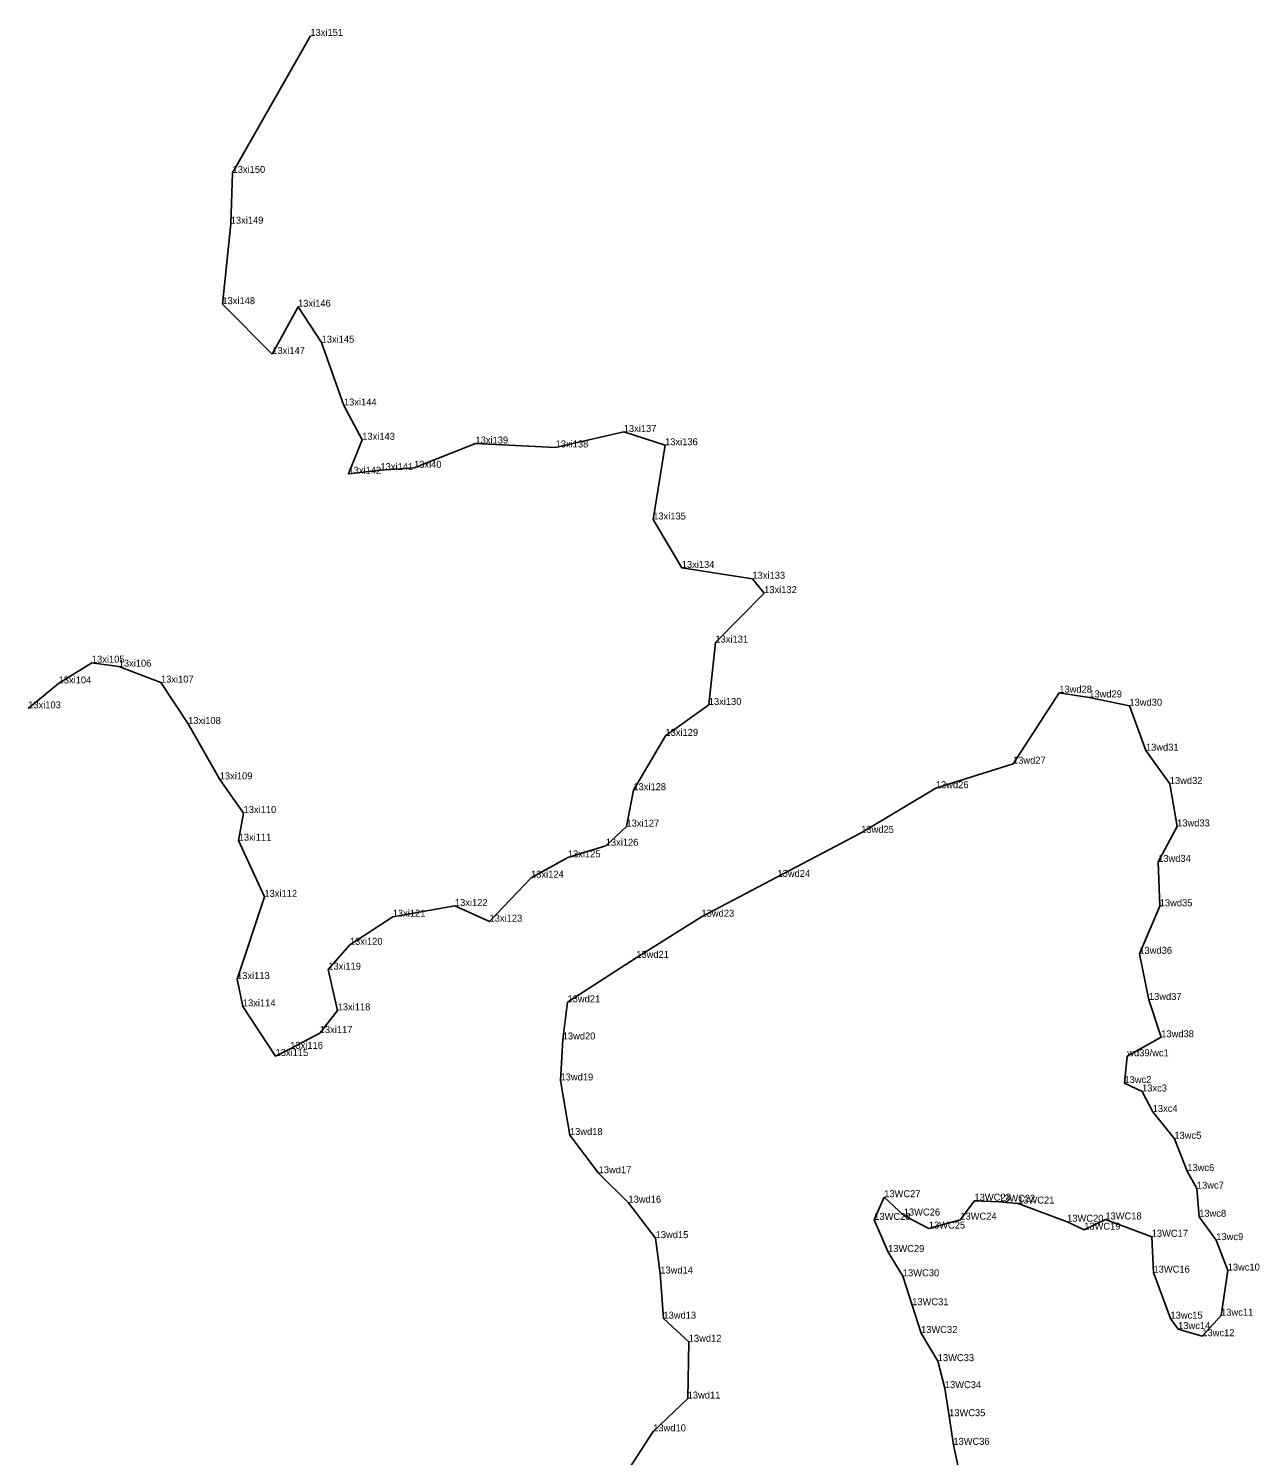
# Model space of a CAD drawing. Extents: x 2072529 to 2267990, y 436423 to 470008.
# Drawn here: x 2249662 to 2250544, y 445372 to 446395 of the extents above; entities that cross this region are included whole.
import ezdxf

# ---------------------------------------------------------------- set-up
doc = ezdxf.new("R2010")
doc.units = 0
doc.layers.add('Level 3', color=7, linetype='Continuous')
doc.layers.add('Old_Level_52', color=7, linetype='Continuous')

msp = doc.modelspace()

# ---------------------------------------------------------------- linework, layer by layer
at = {"layer": 'Level 3'}
for p, q in [((2249864.054, 446389.51), (2249864.054, 446389.51)), ((2249808.263, 446291.367), (2249808.263, 446291.367)), ((2249806.952, 446254.92), (2249806.952, 446254.92)), ((2249800.992, 446197.275), (2249800.992, 446197.275)), ((2249855.211, 446195.401), (2249855.211, 446195.401)), ((2249836.743, 446161.549), (2249836.743, 446161.549)), ((2249872.104, 446169.706), (2249872.104, 446169.706)), ((2249888.108, 446124.67), (2249888.108, 446124.67)), ((2250088.644, 446105.724), (2250088.644, 446105.724)), ((2249901.206, 446100.088), (2249901.206, 446100.088)), ((2249982.375, 446097.438), (2249982.375, 446097.438)), ((2250039.816, 446094.602), (2250039.816, 446094.602)), ((2250118.26, 446096.199), (2250118.26, 446096.199)), ((2249938.334, 446080.021), (2249938.334, 446080.021)), ((2249891.368, 446075.752), (2249891.368, 446075.752)), ((2249914.268, 446078.351), (2249914.268, 446078.351)), ((2250109.758, 446042.981), (2250109.758, 446042.981)), ((2250130.226, 446008.305), (2250130.226, 446008.305)), ((2250180.892, 446000.528), (2250180.892, 446000.528)), ((2250189.242, 445990.208), (2250189.242, 445990.208)), ((2250154.331, 445954.77), (2250154.331, 445954.77)), ((2249707.449, 445940.391), (2249707.449, 445940.391)), ((2249726.667, 445937.537), (2249726.667, 445937.537)), ((2249683.597, 445925.496), (2249683.597, 445925.496)), ((2249756.958, 445926.078), (2249756.958, 445926.078)), ((2250400.808, 445918.894), (2250400.808, 445918.894)), ((2250149.577, 445910.129), (2250149.577, 445910.129)), ((2250422.252, 445915.472), (2250422.252, 445915.472)), ((2250451.071, 445909.522), (2250451.071, 445909.522)), ((2249776.429, 445896.462), (2249776.429, 445896.462)), ((2250118.522, 445887.955), (2250118.522, 445887.955)), ((2250462.899, 445877.362), (2250462.899, 445877.362)), ((2250367.641, 445867.985), (2250367.641, 445867.985)), ((2249799.095, 445856.755), (2249799.095, 445856.755)), ((2250095.551, 445849.029), (2250095.551, 445849.029)), ((2250312.343, 445850.441), (2250312.343, 445850.441)), ((2250480.028, 445853.489), (2250480.028, 445853.489)), ((2249816.152, 445832.664), (2249816.152, 445832.664)), ((2250090.612, 445822.894), (2250090.612, 445822.894)), ((2250258.827, 445818.467), (2250258.827, 445818.467)), ((2250485.256, 445823.027), (2250485.256, 445823.027)), ((2249812.635, 445812.868), (2249812.635, 445812.868)), ((2250075.707, 445809.205), (2250075.707, 445809.205)), ((2250048.591, 445800.888), (2250048.591, 445800.888)), ((2250471.66, 445797.663), (2250471.66, 445797.663)), ((2250022.224, 445786.308), (2250022.224, 445786.308)), ((2250198.833, 445786.89), (2250198.833, 445786.89)), ((2249831.1, 445772.602), (2249831.1, 445772.602)), ((2249967.659, 445766.044), (2249967.659, 445766.044)), ((2250472.787, 445765.849), (2250472.787, 445765.849)), ((2249923.047, 445758.366), (2249923.047, 445758.366)), ((2249992.453, 445754.848), (2249992.453, 445754.848)), ((2250144.364, 445758.387), (2250144.364, 445758.387)), ((2249892.349, 445738.224), (2249892.349, 445738.224)), ((2250097.596, 445728.876), (2250097.596, 445728.876)), ((2250458.197, 445731.761), (2250458.197, 445731.761)), ((2249811.487, 445713.658), (2249811.487, 445713.658)), ((2249876.876, 445720.427), (2249876.876, 445720.427)), ((2249815.634, 445694.123), (2249815.634, 445694.123)), ((2249883.596, 445691.254), (2249883.596, 445691.254)), ((2250048.349, 445697.048), (2250048.349, 445697.048)), ((2250465.048, 445698.73), (2250465.048, 445698.73)), ((2249870.754, 445675.001), (2249870.754, 445675.001)), ((2250473.878, 445671.975), (2250473.878, 445671.975)), ((2249849.636, 445663.68), (2249849.636, 445663.68)), ((2250044.926, 445670.395), (2250044.926, 445670.395)), ((2249839.095, 445658.543), (2249839.095, 445658.543)), ((2250449.561, 445658.346), (2250449.561, 445658.346)), ((2250043.337, 445641.028), (2250043.337, 445641.028)), ((2250447.503, 445639.154), (2250447.503, 445639.154)), ((2250460.153, 445633.119), (2250460.153, 445633.119)), ((2250467.761, 445618.475), (2250467.761, 445618.475)), ((2250050.081, 445601.94), (2250050.081, 445601.94)), ((2250483.307, 445599.234), (2250483.307, 445599.234)), ((2250070.663, 445574.539), (2250070.663, 445574.539)), ((2250492.548, 445576.113), (2250492.548, 445576.113)), ((2250499.436, 445563.489), (2250499.436, 445563.489)), ((2250092.011, 445553.379), (2250092.011, 445553.379)), ((2250275.304, 445557.376), (2250275.304, 445557.376)), ((2250340.03, 445554.884), (2250340.03, 445554.884)), ((2250357.553, 445554.082), (2250357.553, 445554.082)), ((2250371.29, 445552.832), (2250371.29, 445552.832)), ((2250268.196, 445541.116), (2250268.196, 445541.116)), ((2250289.359, 445544.245), (2250289.359, 445544.245)), ((2250329.879, 445541.272), (2250329.879, 445541.272)), ((2250406.433, 445539.779), (2250406.433, 445539.779)), ((2250433.848, 445541.429), (2250433.848, 445541.429)), ((2250501.071, 445543.349), (2250501.071, 445543.349)), ((2250111.517, 445528.038), (2250111.517, 445528.038)), ((2250307.285, 445534.902), (2250307.285, 445534.902)), ((2250418.659, 445534.094), (2250418.659, 445534.094)), ((2250467.078, 445529.007), (2250467.078, 445529.007)), ((2250278.091, 445518.097), (2250278.091, 445518.097)), ((2250513.323, 445526.62), (2250513.323, 445526.62)), ((2250114.867, 445502.675), (2250114.867, 445502.675)), ((2250288.716, 445500.696), (2250288.716, 445500.696)), ((2250468.341, 445503.313), (2250468.341, 445503.313)), ((2250521.505, 445504.804), (2250521.505, 445504.804)), ((2250295.375, 445479.962), (2250295.375, 445479.962)), ((2250117.098, 445470.353), (2250117.098, 445470.353)), ((2250480.512, 445470.342), (2250480.512, 445470.342)), ((2250516.789, 445472.496), (2250516.789, 445472.496)), ((2250301.746, 445460.062), (2250301.746, 445460.062)), ((2250485.992, 445462.892), (2250485.992, 445462.892)), ((2250503.336, 445457.758), (2250503.336, 445457.758)), ((2250135.235, 445453.754), (2250135.235, 445453.754)), ((2250313.716, 445439.903), (2250313.716, 445439.903)), ((2250318.777, 445420.55), (2250318.777, 445420.55)), ((2250134.485, 445413.117), (2250134.485, 445413.117)), ((2250321.832, 445400.469), (2250321.832, 445400.469)), ((2250109.769, 445389.585), (2250109.769, 445389.585)), ((2250324.878, 445379.928), (2250324.878, 445379.928))]:
    msp.add_line(p, q, dxfattribs=at)
at = {"layer": 'Old_Level_52'}
for points in [[(2249836.743, 446161.549), (2249800.992, 446197.275), (2249806.952, 446254.92), (2249808.263, 446291.367), (2249864.054, 446389.51)], [(2249661.789, 445907.651), (2249683.597, 445925.496), (2249707.449, 445940.391), (2249726.667, 445937.537), (2249756.958, 445926.078), (2249776.429, 445896.462), (2249799.095, 445856.755), (2249816.152, 445832.664), (2249812.635, 445812.868), (2249831.1, 445772.602), (2249811.487, 445713.658), (2249815.634, 445694.123), (2249839.095, 445658.543), (2249849.636, 445663.68), (2249870.754, 445675.001), (2249883.596, 445691.254), (2249876.876, 445720.427), (2249892.349, 445738.224), (2249923.047, 445758.366), (2249967.659, 445766.044), (2249992.453, 445754.848), (2250022.224, 445786.308), (2250048.591, 445800.888), (2250075.707, 445809.205), (2250090.612, 445822.894), (2250095.551, 445849.029), (2250118.522, 445887.955), (2250149.577, 445910.129), (2250154.331, 445954.77), (2250189.242, 445990.208), (2250180.892, 446000.528), (2250130.226, 446008.305), (2250109.758, 446042.981), (2250118.26, 446096.199), (2250088.644, 446105.724), (2250039.816, 446094.602), (2249982.375, 446097.438), (2249938.334, 446080.021), (2249914.268, 446078.351), (2249891.368, 446075.752), (2249901.206, 446100.088), (2249888.108, 446124.67), (2249872.104, 446169.706), (2249855.211, 446195.401), (2249836.743, 446161.549)], [(2250072.796, 445332.468), (2250109.769, 445389.585), (2250134.485, 445413.117), (2250135.235, 445453.754), (2250117.098, 445470.353), (2250114.867, 445502.675), (2250111.517, 445528.038), (2250092.011, 445553.379), (2250070.663, 445574.539), (2250050.081, 445601.94), (2250043.337, 445641.028), (2250044.926, 445670.395), (2250048.349, 445697.048), (2250097.596, 445728.876), (2250144.364, 445758.387), (2250198.833, 445786.89), (2250258.827, 445818.467), (2250312.343, 445850.441), (2250367.641, 445867.985), (2250400.808, 445918.894), (2250422.252, 445915.472), (2250451.071, 445909.522), (2250462.899, 445877.362), (2250480.028, 445853.489), (2250485.256, 445823.027), (2250471.66, 445797.663), (2250472.787, 445765.849), (2250458.197, 445731.761), (2250465.048, 445698.73), (2250473.878, 445671.975), (2250449.561, 445658.346), (2250447.503, 445639.154), (2250460.153, 445633.119), (2250467.761, 445618.475), (2250483.307, 445599.234), (2250492.548, 445576.113), (2250499.436, 445563.489), (2250501.071, 445543.349), (2250513.323, 445526.62), (2250521.505, 445504.804), (2250516.789, 445472.496), (2250503.336, 445457.758), (2250485.992, 445462.892), (2250480.512, 445470.342), (2250468.341, 445503.313), (2250467.078, 445529.007), (2250433.848, 445541.429), (2250418.659, 445534.094), (2250406.433, 445539.779), (2250371.29, 445552.832), (2250357.553, 445554.082), (2250340.03, 445554.884), (2250329.879, 445541.272), (2250307.285, 445534.902), (2250289.359, 445544.245), (2250275.304, 445557.376), (2250268.196, 445541.116), (2250278.091, 445518.097), (2250288.716, 445500.696), (2250295.375, 445479.962), (2250301.746, 445460.062), (2250313.716, 445439.903), (2250318.777, 445420.55), (2250321.832, 445400.469), (2250324.878, 445379.928), (2250329.288, 445359.697)]]:
    msp.add_lwpolyline(points, dxfattribs=at)

# ---------------------------------------------------------------- texts
for s, p in [('13xi151', (2249864.054, 446389.51)), ('13xi150', (2249808.263, 446291.367)), ('13xi149', (2249806.952, 446254.92)), ('13xi148', (2249800.992, 446197.275)), ('13xi146', (2249855.211, 446195.401)), ('13xi145', (2249872.104, 446169.706)), ('13xi147', (2249836.743, 446161.549)), ('13xi144', (2249888.108, 446124.67)), ('13xi137', (2250088.644, 446105.724)), ('13xi143', (2249901.206, 446100.088)), ('13xi139', (2249982.375, 446097.438)), ('13xi136', (2250118.26, 446096.199)), ('13xi138', (2250039.816, 446094.602)), ('13xi142', (2249891.368, 446075.752)), ('13xi141', (2249914.268, 446078.351)), ('13xi40', (2249938.334, 446080.021)), ('13xi135', (2250109.758, 446042.981)), ('13xi134', (2250130.226, 446008.305)), ('13xi133', (2250180.892, 446000.528)), ('13xi132', (2250189.242, 445990.208)), ('13xi131', (2250154.331, 445954.77)), ('13xi105', (2249707.449, 445940.391)), ('13xi106', (2249726.667, 445937.537)), ('13xi104', (2249683.597, 445925.496)), ('13xi107', (2249756.958, 445926.078)), ('13wd28', (2250400.808, 445918.894)), ('13wd29', (2250422.252, 445915.472)), ('13xi103', (2249661.789, 445907.651)), ('13xi130', (2250149.577, 445910.129)), ('13wd30', (2250451.071, 445909.522)), ('13xi108', (2249776.429, 445896.462)), ('13xi129', (2250118.522, 445887.955)), ('13wd31', (2250462.899, 445877.362)), ('13wd27', (2250367.641, 445867.985)), ('13xi109', (2249799.095, 445856.755)), ('13wd26', (2250312.343, 445850.441)), ('13wd32', (2250480.028, 445853.489)), ('13xi128', (2250095.551, 445849.029)), ('13xi110', (2249816.152, 445832.664)), ('13xi127', (2250090.612, 445822.894)), ('13wd33', (2250485.256, 445823.027)), ('13xi111', (2249812.635, 445812.868)), ('13xi126', (2250075.707, 445809.205)), ('13wd25', (2250258.827, 445818.467)), ('13xi125', (2250048.591, 445800.888)), ('13wd34', (2250471.66, 445797.663)), ('13xi124', (2250022.224, 445786.308)), ('13wd24', (2250198.833, 445786.89)), ('13xi112', (2249831.1, 445772.602)), ('13xi121', (2249923.047, 445758.366)), ('13xi122', (2249967.659, 445766.044)), ('13wd23', (2250144.364, 445758.387)), ('13wd35', (2250472.787, 445765.849)), ('13xi123', (2249992.453, 445754.848)), ('13xi120', (2249892.349, 445738.224)), ('13wd21', (2250097.596, 445728.876)), ('13wd36', (2250458.197, 445731.761)), ('13xi119', (2249876.876, 445720.427)), ('13xi113', (2249811.487, 445713.658)), ('13wd21', (2250048.349, 445697.048)), ('13wd37', (2250465.048, 445698.73)), ('13xi114', (2249815.634, 445694.123)), ('13xi118', (2249883.596, 445691.254)), ('13xi117', (2249870.754, 445675.001)), ('13wd20', (2250044.926, 445670.395)), ('13wd38', (2250473.878, 445671.975)), ('13xi115', (2249839.095, 445658.543)), ('13xi116', (2249849.636, 445663.68)), ('wd39/wc1', (2250449.561, 445658.346)), ('13wd19', (2250043.337, 445641.028)), ('13wc2', (2250447.503, 445639.154)), ('13xc3', (2250460.153, 445633.119)), ('13xc4', (2250467.761, 445618.475)), ('13wd18', (2250050.081, 445601.94)), ('13wc5', (2250483.307, 445599.234)), ('13wd17', (2250070.663, 445574.539)), ('13wc6', (2250492.548, 445576.113)), ('13wc7', (2250499.436, 445563.489)), ('13wd16', (2250092.011, 445553.379)), ('13WC27', (2250275.304, 445557.376)), ('13WC23', (2250340.03, 445554.884)), ('13WC22', (2250357.553, 445554.082)), ('13WC26', (2250289.359, 445544.245)), ('13WC21', (2250371.29, 445552.832)), ('13wc8', (2250501.071, 445543.349)), ('13WC28', (2250268.196, 445541.116)), ('13WC25', (2250307.285, 445534.902)), ('13WC24', (2250329.879, 445541.272)), ('13WC20', (2250406.433, 445539.779)), ('13WC19', (2250418.659, 445534.094)), ('13WC18', (2250433.848, 445541.429)), ('13wd15', (2250111.517, 445528.038)), ('13WC17', (2250467.078, 445529.007)), ('13wc9', (2250513.323, 445526.62)), ('13WC29', (2250278.091, 445518.097)), ('13wd14', (2250114.867, 445502.675)), ('13WC16', (2250468.341, 445503.313)), ('13wc10', (2250521.505, 445504.804)), ('13WC30', (2250288.716, 445500.696)), ('13WC31', (2250295.375, 445479.962)), ('13wc11', (2250516.789, 445472.496)), ('13wd13', (2250117.098, 445470.353)), ('13wc15', (2250480.512, 445470.342)), ('13wc14', (2250485.992, 445462.892)), ('13wd12', (2250135.235, 445453.754)), ('13WC32', (2250301.746, 445460.062)), ('13wc12', (2250503.336, 445457.758)), ('13WC33', (2250313.716, 445439.903)), ('13WC34', (2250318.777, 445420.55)), ('13wd11', (2250134.485, 445413.117)), ('13WC35', (2250321.832, 445400.469)), ('13wd10', (2250109.769, 445389.585)), ('13WC36', (2250324.878, 445379.928))]:
    msp.add_text(s, height=5).set_placement(p)

doc.saveas('drawing.dxf')
